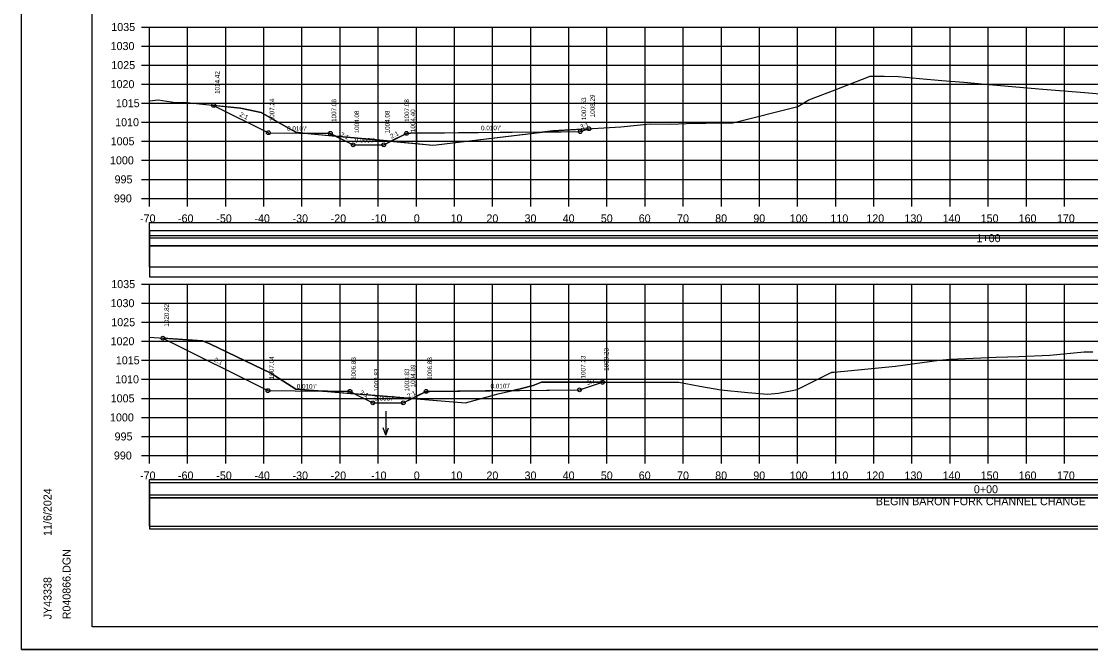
# Model space of a CAD drawing. Extents: x 1370565 to 1374448, y 301010 to 304637.
# Drawn here: x 1373947.9 to 1374228.4, y 301093 to 301257.9 of the extents above; entities that cross this region are included whole.
import ezdxf

# ---------------------------------------------------------------- set-up
doc = ezdxf.new("R2010")
doc.units = 0
for name, color, linetype in [('Default', 7, 'Continuous'), ('R_Axis', 7, 'Continuous'), ('R_Axis Annot', 7, 'Continuous'), ('R_Border', 7, 'Continuous'), ('R_Contours', 7, 'Continuous'), ('R_Drive', 7, 'Continuous'), ('R_Exist Surface', 7, 'Continuous'), ('R_Fin Surface', 7, 'Continuous'), ('R_Grid', 7, 'Continuous'), ('R_No Plot', 7, 'Continuous'), ('R_Water Annot', 7, 'Continuous'), ('R_Xsect Elev', 7, 'Continuous'), ('R_Xsect Slope', 7, 'Continuous')]:
    doc.layers.add(name, color=color, linetype=linetype)

msp = doc.modelspace()

# ---------------------------------------------------------------- linework, layer by layer
at = {"layer": 'Default'}
for points in [[(1373981.44, 301201.08), (1374421.61, 301201.08), (1374421.61, 301205.07), (1373981.44, 301205.07)], [(1373981.44, 301193.5), (1374421.61, 301193.5), (1374421.61, 301201.65), (1373981.44, 301201.65)], [(1373981.44, 301133.58), (1374421.61, 301133.58), (1374421.61, 301137.57), (1373981.44, 301137.57)], [(1373981.44, 301125.35), (1374421.61, 301125.35), (1374421.61, 301133.5), (1373981.44, 301133.5)]]:
    msp.add_lwpolyline(points, close=True, dxfattribs=at)
at = {"layer": 'R_Axis'}
for p, q in [((1373979.42, 301256.45), (1373981.52, 301256.45)), ((1373981.52, 301211.45), (1373981.52, 301256.45)), ((1373979.42, 301251.45), (1373981.52, 301251.45)), ((1373979.42, 301246.45), (1373981.52, 301246.45)), ((1373979.42, 301241.45), (1373981.52, 301241.45)), ((1373979.42, 301236.45), (1373981.52, 301236.45)), ((1373979.42, 301231.45), (1373981.52, 301231.45)), ((1373979.42, 301226.45), (1373981.52, 301226.45)), ((1373979.42, 301221.45), (1373981.52, 301221.45)), ((1373979.42, 301216.45), (1373981.52, 301216.45)), ((1373979.42, 301211.45), (1373981.52, 301211.45)), ((1373981.52, 301211.45), (1374421.52, 301211.45)), ((1373981.52, 301209.35), (1373981.52, 301211.45)), ((1373991.52, 301209.35), (1373991.52, 301211.45)), ((1374001.52, 301209.35), (1374001.52, 301211.45)), ((1374011.52, 301209.35), (1374011.52, 301211.45)), ((1374021.52, 301209.35), (1374021.52, 301211.45)), ((1374031.52, 301209.35), (1374031.52, 301211.45)), ((1374041.52, 301209.35), (1374041.52, 301211.45)), ((1374051.52, 301209.35), (1374051.52, 301211.45)), ((1374061.52, 301209.35), (1374061.52, 301211.45)), ((1374071.52, 301209.35), (1374071.52, 301211.45)), ((1374081.52, 301209.35), (1374081.52, 301211.45)), ((1374091.52, 301209.35), (1374091.52, 301211.45)), ((1374101.52, 301209.35), (1374101.52, 301211.45)), ((1374111.52, 301209.35), (1374111.52, 301211.45)), ((1374121.52, 301209.35), (1374121.52, 301211.45)), ((1374131.52, 301209.35), (1374131.52, 301211.45)), ((1374141.52, 301209.35), (1374141.52, 301211.45)), ((1374151.52, 301209.35), (1374151.52, 301211.45)), ((1374161.52, 301209.35), (1374161.52, 301211.45)), ((1374171.52, 301209.35), (1374171.52, 301211.45)), ((1374181.52, 301209.35), (1374181.52, 301211.45)), ((1374191.52, 301209.35), (1374191.52, 301211.45)), ((1374201.52, 301209.35), (1374201.52, 301211.45)), ((1374211.52, 301209.35), (1374211.52, 301211.45)), ((1374221.52, 301209.35), (1374221.52, 301211.45)), ((1373979.42, 301188.95), (1373981.52, 301188.95)), ((1373981.52, 301143.95), (1373981.52, 301188.95)), ((1373979.42, 301183.95), (1373981.52, 301183.95)), ((1373979.42, 301178.95), (1373981.52, 301178.95)), ((1373979.42, 301173.95), (1373981.52, 301173.95)), ((1373979.42, 301168.95), (1373981.52, 301168.95)), ((1373979.42, 301163.95), (1373981.52, 301163.95)), ((1373979.42, 301158.95), (1373981.52, 301158.95)), ((1373979.42, 301153.95), (1373981.52, 301153.95)), ((1373979.42, 301148.95), (1373981.52, 301148.95)), ((1373979.42, 301143.95), (1373981.52, 301143.95)), ((1373981.52, 301143.95), (1374421.52, 301143.95)), ((1373981.52, 301141.85), (1373981.52, 301143.95)), ((1373991.52, 301141.85), (1373991.52, 301143.95)), ((1374001.52, 301141.85), (1374001.52, 301143.95)), ((1374011.52, 301141.85), (1374011.52, 301143.95)), ((1374021.52, 301141.85), (1374021.52, 301143.95)), ((1374031.52, 301141.85), (1374031.52, 301143.95)), ((1374041.52, 301141.85), (1374041.52, 301143.95)), ((1374051.52, 301141.85), (1374051.52, 301143.95)), ((1374061.52, 301141.85), (1374061.52, 301143.95)), ((1374071.52, 301141.85), (1374071.52, 301143.95)), ((1374081.52, 301141.85), (1374081.52, 301143.95)), ((1374091.52, 301141.85), (1374091.52, 301143.95)), ((1374101.52, 301141.85), (1374101.52, 301143.95)), ((1374111.52, 301141.85), (1374111.52, 301143.95)), ((1374121.52, 301141.85), (1374121.52, 301143.95)), ((1374131.52, 301141.85), (1374131.52, 301143.95)), ((1374141.52, 301141.85), (1374141.52, 301143.95)), ((1374151.52, 301141.85), (1374151.52, 301143.95)), ((1374161.52, 301141.85), (1374161.52, 301143.95)), ((1374171.52, 301141.85), (1374171.52, 301143.95)), ((1374181.52, 301141.85), (1374181.52, 301143.95)), ((1374191.52, 301141.85), (1374191.52, 301143.95)), ((1374201.52, 301141.85), (1374201.52, 301143.95)), ((1374211.52, 301141.85), (1374211.52, 301143.95)), ((1374221.52, 301141.85), (1374221.52, 301143.95))]:
    msp.add_line(p, q, dxfattribs=at)
at = {"layer": 'R_Border'}
for p, q in [((1373966.52, 301098.95), (1373966.52, 301407.14)), ((1373966.52, 301098.95), (1373966.52, 301098.95)), ((1374440.79, 301098.95), (1373966.52, 301098.95))]:
    msp.add_line(p, q, dxfattribs=at)
at = {"layer": 'R_Contours'}
for p, q in [((1374087.33, 301229.22), (1374084.55, 301228.88)), ((1374096.79, 301229.74), (1374087.33, 301229.22)), ((1374021.74, 301228.6), (1374019.92, 301228.8)), ((1374028.95, 301228.53), (1374022.08, 301228.6)), ((1374022.08, 301228.56), (1374030.41, 301227.8)), ((1374030.41, 301227.8), (1374028.95, 301228.53)), ((1374044.83, 301226.47), (1374030.41, 301227.8)), ((1374044.83, 301226.47), (1374051.52, 301225.85)), ((1374084.55, 301228.88), (1374051.52, 301228.55)), ((1374051.52, 301228.55), (1374051.52, 301225.85)), ((1374051.52, 301225.85), (1374051.52, 301228.55)), ((1374100.38, 301163.18), (1374089.26, 301163.18)), ((1374026.87, 301160.85), (1374019.89, 301161.38)), ((1374028.23, 301160.84), (1374026.87, 301160.85)), ((1374026.87, 301160.85), (1374028.23, 301160.75)), ((1374034.09, 301160.78), (1374028.23, 301160.84)), ((1374028.23, 301160.75), (1374035.31, 301160.17)), ((1374035.31, 301160.17), (1374034.09, 301160.78)), ((1374050.4, 301158.93), (1374035.31, 301160.17)), ((1374051.52, 301159.5), (1374050.4, 301158.93)), ((1374051.52, 301159.5), (1374051.52, 301158.84)), ((1374051.52, 301158.84), (1374051.52, 301159.5)), ((1374050.4, 301158.93), (1374051.52, 301158.84))]:
    msp.add_line(p, q, dxfattribs=at)
for points in [[(1374019.92, 301228.8), (1374017.95, 301229.88), (1374010.84, 301233.99), (1374005.39, 301235.13), (1373998.34, 301235.87)], [(1373998.34, 301235.87), (1374012.7, 301228.69), (1374021.74, 301228.6)], [(1374084.55, 301228.88), (1374094.5, 301228.98), (1374096.79, 301229.74)], [(1374022.08, 301228.6), (1374022.08, 301228.56)], [(1374030.41, 301227.8), (1374034.95, 301225.53), (1374042.95, 301225.53), (1374044.83, 301226.47)], [(1374051.52, 301228.55), (1374049.95, 301228.54), (1374048.95, 301228.53), (1374044.83, 301226.47)], [(1374051.52, 301225.85), (1374055.87, 301225.45), (1374056.69, 301225.53), (1374084.55, 301228.88)], [(1374019.89, 301161.38), (1374013.32, 301165.59), (1373997.32, 301173.27), (1373995.42, 301174.07), (1373985.04, 301174.77)], [(1373985.04, 301174.77), (1373985.04, 301174.77)], [(1373985.04, 301174.77), (1374012.59, 301160.99), (1374026.87, 301160.85)], [(1374089.26, 301163.18), (1374084.33, 301163.17), (1374082.16, 301162.35), (1374079.09, 301161.5), (1374076.91, 301161.01)], [(1374076.91, 301161.01), (1374094.33, 301161.18), (1374100.38, 301163.18)], [(1374028.23, 301160.84), (1374028.23, 301160.75)], [(1374028.23, 301160.75), (1374028.23, 301160.84)], [(1374035.31, 301160.17), (1374040.09, 301157.78), (1374048.09, 301157.78), (1374050.4, 301158.93)], [(1374051.52, 301158.84), (1374064.42, 301157.79), (1374072.99, 301160.13), (1374076.91, 301161.01)], [(1374076.91, 301161.01), (1374055.09, 301160.79), (1374054.09, 301160.78), (1374051.52, 301159.5)]]:
    msp.add_lwpolyline(points, dxfattribs=at)
at = {"layer": 'R_Drive'}
for points in [[(1373981.52, 301198.96), (1374421.73, 301198.96), (1374421.73, 301202.96), (1373981.52, 301202.96)], [(1373981.52, 301190.82), (1374421.73, 301190.82), (1374421.73, 301198.96), (1373981.52, 301198.96)], [(1373981.52, 301132.8), (1374421.73, 301132.8), (1374421.73, 301136.79), (1373981.52, 301136.79)], [(1373981.52, 301124.65), (1374421.75, 301124.65), (1374421.75, 301132.8), (1373981.52, 301132.8)]]:
    msp.add_lwpolyline(points, close=True, dxfattribs=at)
at = {"layer": 'R_Exist Surface'}
for points in [[(1373981.52, 301237.08), (1373983.77, 301237.32), (1373988.34, 301236.62), (1373990.53, 301236.69), (1374005.39, 301235.13), (1374010.84, 301233.99), (1374017.95, 301229.88), (1374019.92, 301228.8), (1374022.08, 301228.56), (1374055.87, 301225.45), (1374056.69, 301225.53), (1374087.33, 301229.22), (1374105.11, 301230.2), (1374112.86, 301231.03), (1374118.21, 301230.9), (1374122.4, 301231.08), (1374132.5, 301231.29), (1374134.51, 301231.3), (1374151.58, 301235.56), (1374154.44, 301237.31), (1374161.38, 301239.94), (1374170.52, 301243.53), (1374174.26, 301243.51), (1374177.99, 301243.49), (1374183.48, 301242.94), (1374189.33, 301242.44), (1374195.1, 301241.95), (1374200.74, 301241.48), (1374215.82, 301240.15), (1374226.84, 301239.25), (1374232.78, 301238.71)], [(1373981.52, 301175.01), (1373995.42, 301174.07), (1373997.32, 301173.27), (1374013.32, 301165.59), (1374019.89, 301161.38), (1374028.23, 301160.75), (1374064.42, 301157.79), (1374072.99, 301160.13), (1374079.09, 301161.5), (1374082.16, 301162.35), (1374084.33, 301163.17), (1374089.26, 301163.18), (1374104.01, 301163.18), (1374120.4, 301163.17), (1374125.9, 301162.17), (1374131.41, 301161.16), (1374138.45, 301160.47), (1374143.64, 301160.06), (1374146.5, 301160.31), (1374151.45, 301161.31), (1374160.17, 301165.67), (1374160.4, 301165.77), (1374160.49, 301165.8), (1374161.1, 301165.87), (1374177.18, 301167.39), (1374188.65, 301168.98), (1374191.5, 301169.26), (1374203.59, 301169.75), (1374209.54, 301169.98), (1374217.69, 301170.25), (1374226.65, 301171.2), (1374228.95, 301171.13)]]:
    msp.add_lwpolyline(points, dxfattribs=at)
at = {"layer": 'R_Fin Surface'}
for points in [[(1373998.34, 301235.87), (1374012.7, 301228.69), (1374028.95, 301228.53), (1374034.95, 301225.53), (1374042.95, 301225.53), (1374048.95, 301228.53), (1374049.95, 301228.54), (1374094.5, 301228.98), (1374096.79, 301229.74)], [(1373985.04, 301174.77), (1373985.04, 301174.77), (1374012.59, 301160.99), (1374012.6, 301160.99), (1374034.09, 301160.78), (1374040.09, 301157.78), (1374048.09, 301157.78), (1374054.09, 301160.78), (1374055.09, 301160.79), (1374055.09, 301160.79), (1374094.33, 301161.18), (1374100.38, 301163.18)]]:
    msp.add_lwpolyline(points, dxfattribs=at)
at = {"layer": 'R_Grid'}
for p, q in [((1373981.52, 301256.45), (1374421.52, 301256.45)), ((1373981.52, 301211.45), (1373981.52, 301256.45)), ((1373991.52, 301211.45), (1373991.52, 301256.45)), ((1374001.52, 301211.45), (1374001.52, 301256.45)), ((1374011.52, 301211.45), (1374011.52, 301256.45)), ((1374021.52, 301211.45), (1374021.52, 301256.45)), ((1374031.52, 301211.45), (1374031.52, 301256.45)), ((1374041.52, 301211.45), (1374041.52, 301256.45)), ((1374051.52, 301211.45), (1374051.52, 301256.45)), ((1374061.52, 301211.45), (1374061.52, 301256.45)), ((1374071.52, 301211.45), (1374071.52, 301256.45)), ((1374081.52, 301211.45), (1374081.52, 301256.45)), ((1374091.52, 301211.45), (1374091.52, 301256.45)), ((1374101.52, 301211.45), (1374101.52, 301256.45)), ((1374111.52, 301211.45), (1374111.52, 301256.45)), ((1374121.52, 301211.45), (1374121.52, 301256.45)), ((1374131.52, 301211.45), (1374131.52, 301256.45)), ((1374141.52, 301211.45), (1374141.52, 301256.45)), ((1374151.52, 301211.45), (1374151.52, 301256.45)), ((1374161.52, 301211.45), (1374161.52, 301256.45)), ((1374171.52, 301211.45), (1374171.52, 301256.45)), ((1374181.52, 301211.45), (1374181.52, 301256.45)), ((1374191.52, 301211.45), (1374191.52, 301256.45)), ((1374201.52, 301211.45), (1374201.52, 301256.45)), ((1374211.52, 301211.45), (1374211.52, 301256.45)), ((1374221.52, 301211.45), (1374221.52, 301256.45)), ((1373981.52, 301251.45), (1374421.52, 301251.45)), ((1373981.52, 301246.45), (1374421.52, 301246.45)), ((1373981.52, 301241.45), (1374421.52, 301241.45)), ((1373981.52, 301236.45), (1374421.52, 301236.45)), ((1373981.52, 301231.45), (1374421.52, 301231.45)), ((1373981.52, 301226.45), (1374421.52, 301226.45)), ((1373981.52, 301221.45), (1374421.52, 301221.45)), ((1373981.52, 301216.45), (1374421.52, 301216.45)), ((1373981.52, 301211.45), (1374421.52, 301211.45)), ((1373981.52, 301188.95), (1374421.52, 301188.95)), ((1373981.52, 301143.95), (1373981.52, 301188.95)), ((1373991.52, 301143.95), (1373991.52, 301188.95)), ((1374001.52, 301143.95), (1374001.52, 301188.95)), ((1374011.52, 301143.95), (1374011.52, 301188.95)), ((1374021.52, 301143.95), (1374021.52, 301188.95)), ((1374031.52, 301143.95), (1374031.52, 301188.95)), ((1374041.52, 301143.95), (1374041.52, 301188.95)), ((1374051.52, 301143.95), (1374051.52, 301188.95)), ((1374061.52, 301143.95), (1374061.52, 301188.95)), ((1374071.52, 301143.95), (1374071.52, 301188.95)), ((1374081.52, 301143.95), (1374081.52, 301188.95)), ((1374091.52, 301143.95), (1374091.52, 301188.95)), ((1374101.52, 301143.95), (1374101.52, 301188.95)), ((1374111.52, 301143.95), (1374111.52, 301188.95)), ((1374121.52, 301143.95), (1374121.52, 301188.95)), ((1374131.52, 301143.95), (1374131.52, 301188.95)), ((1374141.52, 301143.95), (1374141.52, 301188.95)), ((1374151.52, 301143.95), (1374151.52, 301188.95)), ((1374161.52, 301143.95), (1374161.52, 301188.95)), ((1374171.52, 301143.95), (1374171.52, 301188.95)), ((1374181.52, 301143.95), (1374181.52, 301188.95)), ((1374191.52, 301143.95), (1374191.52, 301188.95)), ((1374201.52, 301143.95), (1374201.52, 301188.95)), ((1374211.52, 301143.95), (1374211.52, 301188.95)), ((1374221.52, 301143.95), (1374221.52, 301188.95)), ((1373981.52, 301183.95), (1374421.52, 301183.95)), ((1373981.52, 301178.95), (1374421.52, 301178.95)), ((1373981.52, 301173.95), (1374421.52, 301173.95)), ((1373981.52, 301168.95), (1374421.52, 301168.95)), ((1373981.52, 301163.95), (1374421.52, 301163.95)), ((1373981.52, 301158.95), (1374421.52, 301158.95)), ((1373981.52, 301153.95), (1374421.52, 301153.95)), ((1373981.52, 301148.95), (1374421.52, 301148.95)), ((1373981.52, 301143.95), (1374421.52, 301143.95))]:
    msp.add_line(p, q, dxfattribs=at)
at = {"layer": 'R_No Plot'}
msp.add_line((1373947.92, 301092.98), (1374447.92, 301092.98), dxfattribs=at)
for points in [[(1373947.91, 301412.98), (1374447.92, 301412.98), (1374447.92, 301092.98), (1373947.91, 301092.98)], [(1374317.4, 301407.14), (1374346.83, 301407.14), (1374346.83, 301392.32), (1374371, 301392.32), (1374405.8, 301392.32), (1374405.98, 301350.08), (1374440.79, 301350.08), (1374440.79, 301098.95), (1373966.52, 301098.95), (1373966.52, 301407.14)]]:
    msp.add_lwpolyline(points, close=True, dxfattribs=at)
for centre in [(1373998.34, 301235.87), (1374012.7, 301228.69), (1374094.5, 301228.98), (1374096.79, 301229.74), (1374028.95, 301228.53), (1374048.95, 301228.53), (1374034.95, 301225.53), (1374042.95, 301225.53), (1373985.04, 301174.77), (1374100.38, 301163.18), (1374012.59, 301160.99), (1374034.09, 301160.78), (1374054.09, 301160.78), (1374094.33, 301161.18), (1374040.09, 301157.78), (1374048.09, 301157.78)]:
    msp.add_circle(centre, 0.5, dxfattribs=at)
at = {"layer": 'R_Water Annot'}
for p, q in [((1374043.54, 301155.58), (1374043.54, 301149.29)), ((1374043.54, 301149.29), (1374042.84, 301151.22)), ((1374043.54, 301149.29), (1374044.24, 301151.22))]:
    msp.add_line(p, q, dxfattribs=at)
at = {"layer": 'R_Xsect Elev'}
for p, q in [((1374051.52, 301225.85), (1374051.52, 301235.85)), ((1374051.52, 301158.84), (1374051.52, 301168.84))]:
    msp.add_line(p, q, dxfattribs=at)

# ---------------------------------------------------------------- texts
at = {"layer": 'R_Axis Annot'}
for s, p in [('1035', (1373971.5, 301255.4)), ('1030', (1373971.32, 301250.4)), ('1025', (1373971.5, 301245.4)), ('1020', (1373971.32, 301240.4)), ('1015', (1373972.69, 301235.4)), ('1010', (1373972.51, 301230.4)), ('1005', (1373971.34, 301225.4)), ('1000', (1373971.16, 301220.4)), ('995', (1373972.36, 301215.4)), ('990', (1373972.18, 301210.4)), ('-70', (1373979.04, 301205.15)), ('-60', (1373988.99, 301205.15)), ('-50', (1373999.04, 301205.15)), ('-40', (1374009.04, 301205.15)), ('-30', (1374019.04, 301205.15)), ('-20', (1374029.04, 301205.15)), ('-10', (1374039.63, 301205.15)), ('0', (1374050.84, 301205.15)), ('10', (1374060.49, 301205.15)), ('20', (1374069.9, 301205.15)), ('30', (1374079.9, 301205.15)), ('40', (1374089.9, 301205.15)), ('50', (1374099.9, 301205.15)), ('60', (1374109.85, 301205.15)), ('70', (1374119.9, 301205.15)), ('80', (1374129.9, 301205.15)), ('90', (1374139.9, 301205.15)), ('100', (1374149.47, 301205.15)), ('110', (1374160.14, 301205.15)), ('120', (1374169.55, 301205.15)), ('130', (1374179.55, 301205.15)), ('140', (1374189.55, 301205.15)), ('150', (1374199.55, 301205.15)), ('160', (1374209.5, 301205.15)), ('170', (1374219.55, 301205.15)), ('1+00', (1374198.44, 301199.96)), ('1035', (1373971.5, 301187.9)), ('1030', (1373971.32, 301182.9)), ('1025', (1373971.5, 301177.9)), ('1020', (1373971.32, 301172.9)), ('1015', (1373972.69, 301167.9)), ('1010', (1373972.51, 301162.9)), ('1005', (1373971.34, 301157.9)), ('1000', (1373971.16, 301152.9)), ('995', (1373972.36, 301147.9)), ('990', (1373972.18, 301142.9)), ('-70', (1373979.04, 301137.65)), ('-60', (1373988.99, 301137.65)), ('-50', (1373999.04, 301137.65)), ('-40', (1374009.04, 301137.65)), ('-30', (1374019.04, 301137.65)), ('-20', (1374029.04, 301137.65)), ('-10', (1374039.63, 301137.65)), ('0', (1374050.84, 301137.65)), ('10', (1374060.49, 301137.65)), ('20', (1374069.9, 301137.65)), ('30', (1374079.9, 301137.65)), ('40', (1374089.9, 301137.65)), ('50', (1374099.9, 301137.65)), ('60', (1374109.85, 301137.65)), ('70', (1374119.9, 301137.65)), ('80', (1374129.9, 301137.65)), ('90', (1374139.9, 301137.65)), ('100', (1374149.47, 301137.65)), ('110', (1374160.14, 301137.65)), ('120', (1374169.55, 301137.65)), ('130', (1374179.55, 301137.65)), ('140', (1374189.55, 301137.65)), ('150', (1374199.55, 301137.65)), ('160', (1374209.5, 301137.65)), ('170', (1374219.55, 301137.65)), ('0+00', (1374197.76, 301134.04)), ('BEGIN BARON FORK CHANNEL CHANGE', (1374172.04, 301130.89))]:
    msp.add_text(s, height=2.1, dxfattribs=at).set_placement(p)
at = {"layer": 'R_Border'}
for s, p in [('11/6/2024', (1373955.82, 301122.84)), ('R040866.DGN', (1373960.81, 301100.94)), ('JY43338', (1373955.82, 301100.94))]:
    msp.add_text(s, height=2.1, rotation=90, dxfattribs=at).set_placement(p)
at = {"layer": 'R_Xsect Elev'}
for s, p in [('1014.42', (1373999.89, 301238.87)), ('1007.53', (1374096.05, 301231.98)), ('1008.29', (1374098.34, 301232.74)), ('1007.24', (1374014.25, 301231.69)), ('1007.08', (1374030.5, 301231.53)), ('1007.08', (1374049.61, 301231.53)), ('1004.08', (1374036.5, 301228.53)), ('1004.08', (1374044.5, 301228.53)), ('1004.40', (1374051.22, 301228.85)), ('1020.82', (1373986.59, 301177.77)), ('1009.23', (1374101.93, 301166.18)), ('1007.04', (1374014.14, 301163.99)), ('1006.83', (1374035.64, 301163.78)), ('1004.89', (1374051.22, 301161.84)), ('1006.83', (1374055.64, 301163.78)), ('1007.23', (1374095.88, 301164.18)), ('1003.83', (1374041.64, 301160.78)), ('1003.83', (1374049.64, 301160.78))]:
    msp.add_text(s, height=1.2, rotation=90, dxfattribs=at).set_placement(p)
at = {"layer": 'R_Xsect Slope'}
for s, rotation, p in [('2:1', 333.4349, (1374005, 301233.1)), ("0.010'/'", 359.4271, (1374017.61, 301229.24)), ("0.010'/'", 0.5729, (1374068.49, 301229.32)), ('3:1', 18.2629, (1374094.7, 301229.58)), ('2:1', 333.4349, (1374031.43, 301227.85)), ("0.000'/'", 360, (1374035.34, 301226.13)), ('2:1', 26.5651, (1374044.98, 301227.1)), ('2:1', 333.4349, (1373998.3, 301168.7)), ("0.010'/'", 359.4271, (1374020.13, 301161.52)), ("0.010'/'", 0.5729, (1374070.98, 301161.55)), ('3:1', 18.2629, (1374096.41, 301162.39)), ('2:1', 333.4349, (1374036.57, 301160.1)), ("0.000'/'", 360, (1374040.48, 301158.38)), ('2:1', 26.5651, (1374049.48, 301158.94))]:
    msp.add_text(s, height=1.2, rotation=rotation, dxfattribs=at).set_placement(p)

doc.saveas('drawing.dxf')
